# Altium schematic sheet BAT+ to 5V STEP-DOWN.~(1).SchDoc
size A3; SheetNumber: 11; SheetTotal: 12
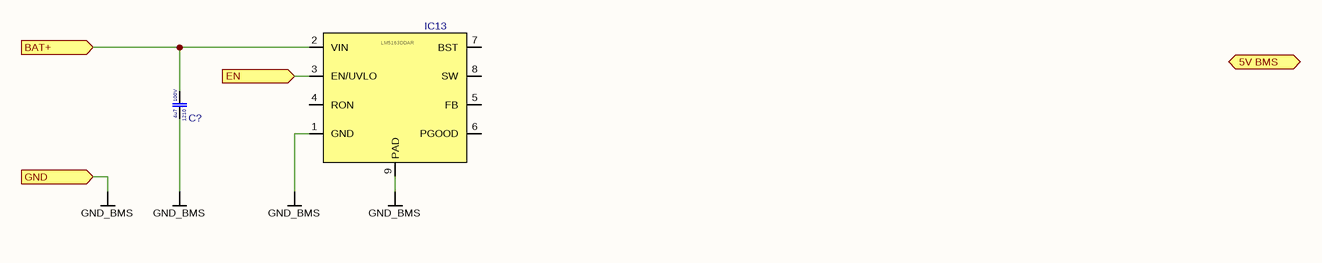
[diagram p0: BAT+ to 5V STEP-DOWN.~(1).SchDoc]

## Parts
C?  Voltage Rating: 100V  Case Code (Imperial): 1210  Capacitance: 4u7  [CAP_1210]  (hidden comment: HMK325C7475KN-TE)
IC13  LM5163DDAR  [ESOP-8]

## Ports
5V BMS (bidir, see BMS[4B], MCU[1B]), BAT+ (in, see BMS[4B], BMS[1A], BQ76952 BMS[1A]), EN (in, see BMS[4B]), GND (in, see BMS[4B], BQ76952 BMS[1D], MCU[1C])

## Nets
GND_BMS: C?.1 IC13.1(GND) IC13.9(PAD) ; port GND
BAT+: C?.2 IC13.2(VIN) ; port BAT+
EN: IC13.3(EN/UVLO) ; port EN

Not connected (* = marked no-connect by the designer): IC13 4(RON) 5(FB) 6(PGOOD) 7(BST) 8(SW)

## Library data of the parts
C? = HMK325C7475KN-TE: Cap 4.7uF 100V 1210 X7R; Manufacturer: Taiyo Yuden
IC13 = LM5163DDAR: DCDC Step-down Converter 9~100Vin 0.5Aout; Manufacturer: Texas Instruments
